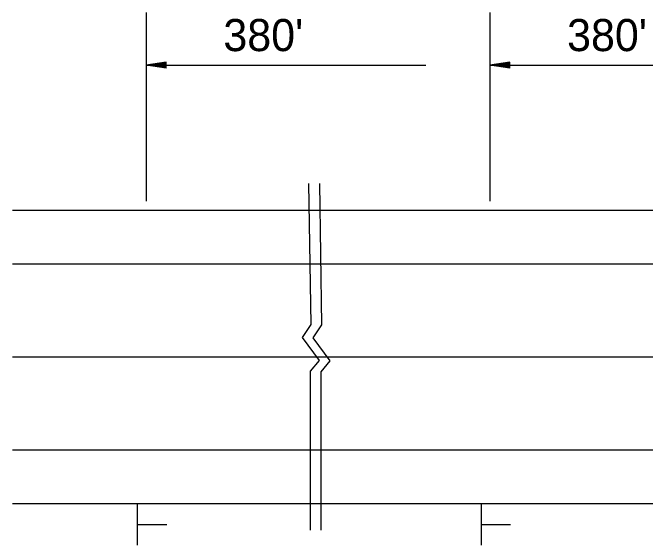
# Model space of a CAD drawing. Extents: x 1806907 to 1812607, y 675071 to 676228.
# Drawn here: x 1809227.5 to 1809345.6, y 675743.3 to 675842.8 of the extents above; entities that cross this region are included whole.
import ezdxf

# ---------------------------------------------------------------- set-up
doc = ezdxf.new("R2010")
doc.units = 0
doc.layers.add('Default', color=7, linetype='Continuous')

msp = doc.modelspace()

# ---------------------------------------------------------------- linework, layer by layer
at = {"layer": 'Default'}
for p, q in [((1809252.43, 675842.78), (1809252.43, 675807.57)), ((1809316.59, 675842.78), (1809316.59, 675807.57)), ((1809256.18, 675833.55), (1809252.43, 675832.99)), ((1809256.18, 675833.45), (1809253.05, 675832.99)), ((1809256.18, 675833.36), (1809253.7, 675832.99)), ((1809256.18, 675833.27), (1809254.32, 675832.99)), ((1809256.18, 675832.42), (1809256.18, 675833.55)), ((1809320.34, 675833.55), (1809316.59, 675832.99)), ((1809320.34, 675833.45), (1809317.21, 675832.99)), ((1809320.34, 675833.36), (1809317.86, 675832.99)), ((1809320.34, 675833.27), (1809318.48, 675832.99)), ((1809320.34, 675832.42), (1809320.34, 675833.55)), ((1809252.43, 675832.99), (1809304.62, 675832.99)), ((1809256.18, 675832.42), (1809252.43, 675832.99)), ((1809256.18, 675832.52), (1809253.05, 675832.99)), ((1809256.18, 675832.61), (1809253.7, 675832.99)), ((1809256.18, 675832.71), (1809254.32, 675832.99)), ((1809256.18, 675833.17), (1809254.96, 675832.99)), ((1809256.18, 675832.8), (1809254.96, 675832.99)), ((1809256.18, 675833.07), (1809255.58, 675832.99)), ((1809256.18, 675832.9), (1809255.58, 675832.99)), ((1809316.59, 675832.99), (1809368.78, 675832.99)), ((1809320.34, 675832.42), (1809316.59, 675832.99)), ((1809320.34, 675832.52), (1809317.21, 675832.99)), ((1809320.34, 675832.61), (1809317.86, 675832.99)), ((1809320.34, 675832.71), (1809318.48, 675832.99)), ((1809320.34, 675833.17), (1809319.12, 675832.99)), ((1809320.34, 675832.8), (1809319.12, 675832.99)), ((1809320.34, 675833.07), (1809319.75, 675832.99)), ((1809320.34, 675832.9), (1809319.75, 675832.99)), ((1809227.51, 675805.87), (1810285.86, 675805.87)), ((1809227.51, 675795.87), (1809776.27, 675795.87)), ((1809227.51, 675778.48), (1809663.82, 675778.48)), ((1809227.51, 675761.1), (1809776.27, 675761.1)), ((1809227.51, 675751.1), (1810285.86, 675751.1)), ((1809250.84, 675743.28), (1809250.84, 675751.1)), ((1809315, 675743.28), (1809315, 675751.1)), ((1809250.96, 675747.17), (1809256.3, 675747.17)), ((1809315.12, 675747.17), (1809320.46, 675747.17))]:
    msp.add_line(p, q, dxfattribs=at)
for points in [[(1809282.76, 675810.87), (1809283.16, 675784.54), (1809281.54, 675782.13), (1809284.7, 675777.8), (1809283.04, 675775.8), (1809283.03, 675746.1)], [(1809284.76, 675810.87), (1809285.16, 675784.46), (1809283.54, 675782.04), (1809286.7, 675777.71), (1809285.04, 675775.71), (1809285.03, 675746.1)]]:
    msp.add_lwpolyline(points, dxfattribs=at)

# ---------------------------------------------------------------- texts
for p in [(1809266.84, 675835.59), (1809331, 675835.59)]:
    msp.add_text("380'", height=6, dxfattribs=at).set_placement(p)

doc.saveas('drawing.dxf')
